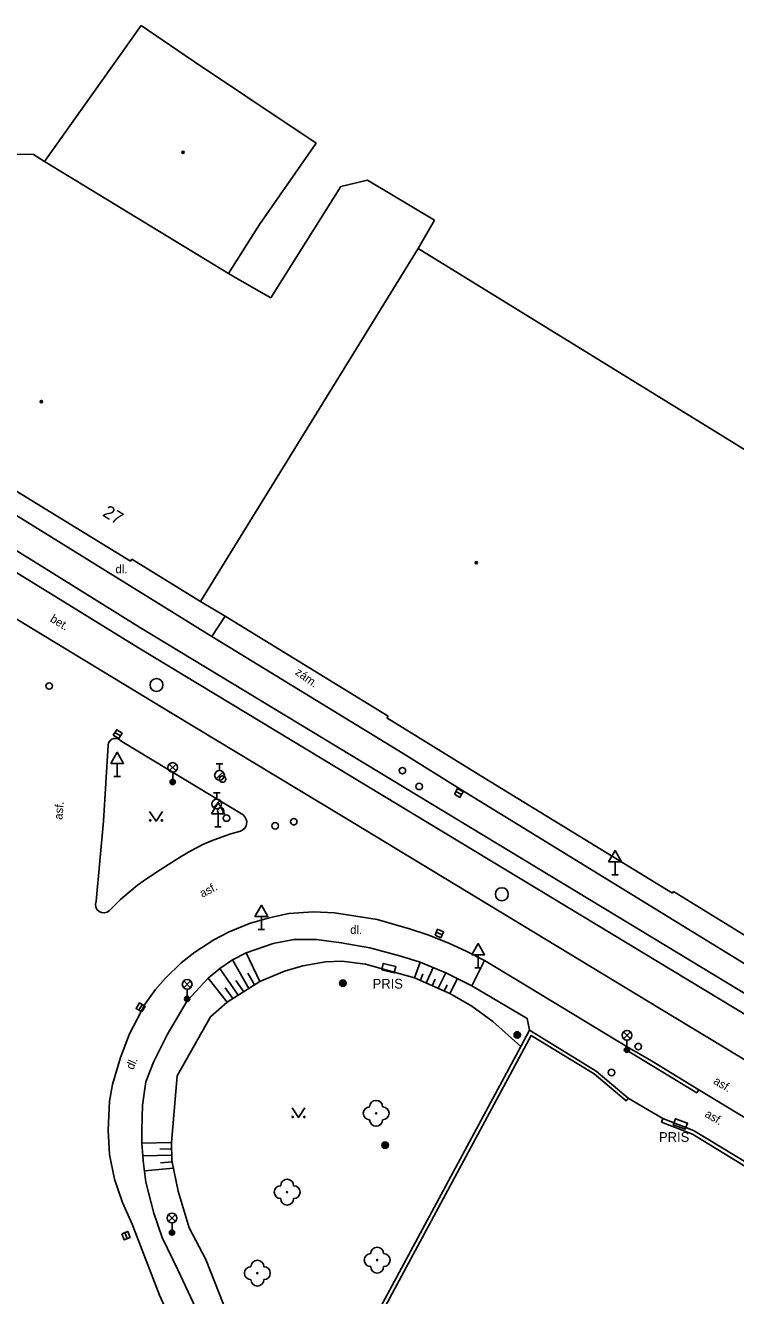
# Model space of a CAD drawing. Extents: x -598341 to -594502, y -1162301 to -1161406.
# Drawn here: x -597632.3 to -597577.4, y -1161626.1 to -1161527.8 of the extents above; entities that cross this region are included whole.
import ezdxf

# ---------------------------------------------------------------- set-up
doc = ezdxf.new("R2010")
doc.units = 0
for name, color, linetype in [('Vrstva 10', 7, 'Continuous'), ('Vrstva 11', 7, 'Continuous'), ('Vrstva 13', 7, 'Continuous'), ('Vrstva 14', 7, 'Continuous'), ('Vrstva 15', 7, 'Continuous'), ('Vrstva 22', 7, 'Continuous'), ('Vrstva 24', 7, 'Continuous'), ('Vrstva 25', 7, 'Continuous'), ('Vrstva 27', 7, 'Continuous'), ('Vrstva 28', 7, 'Continuous'), ('Vrstva 33', 7, 'Continuous'), ('Vrstva 34', 7, 'Continuous'), ('Vrstva 36', 7, 'Continuous'), ('Vrstva 39', 7, 'Continuous'), ('Vrstva 40', 7, 'Continuous'), ('Vrstva 41', 7, 'Continuous'), ('Vrstva 46', 7, 'Continuous'), ('Vrstva 5', 7, 'Continuous'), ('Vrstva 7', 7, 'Continuous'), ('Vrstva 8', 7, 'Continuous')]:
    doc.layers.add(name, color=color, linetype=linetype)

msp = doc.modelspace()

# ---------------------------------------------------------------- linework, layer by layer
at = {"layer": 'Vrstva 10'}
for p, q in [((-597624.88, -1161583.22), (-597615.5, -1161588.89)), ((-597594.17, -1161601.76), (-597596.82, -1161600.16)), ((-597624.07, -1161620.55), (-597621.97, -1161626.04)), ((-597621.97, -1161626.04), (-597612.47, -1161646.5))]:
    msp.add_line(p, q, dxfattribs=at)
for points in [[(-597648.34, -1161556.03), (-597646.18, -1161557.58), (-597617.91, -1161575.1)], [(-597617.91, -1161575.1), (-597603.13, -1161584.15)], [(-597625.93, -1161583.5), (-597625.89, -1161583.33), (-597625.77, -1161583.14), (-597625.64, -1161583.04), (-597625.5, -1161582.99), (-597625.33, -1161582.97), (-597625.16, -1161583.01), (-597624.88, -1161583.22)], [(-597626.86, -1161595.57), (-597626.28, -1161589.39), (-597625.93, -1161583.5)], [(-597603.13, -1161584.15), (-597598.66, -1161586.94), (-597567.48, -1161606.1)], [(-597615.5, -1161588.89), (-597615.35, -1161589.04), (-597615.25, -1161589.24), (-597615.21, -1161589.4), (-597615.23, -1161589.58), (-597615.27, -1161589.75), (-597615.36, -1161589.92), (-597615.51, -1161590.04), (-597615.7, -1161590.16), (-597616.44, -1161590.37), (-597617.17, -1161590.61), (-597617.95, -1161590.91), (-597618.6, -1161591.19), (-597619.53, -1161591.67), (-597620.29, -1161592.11), (-597621.25, -1161592.74), (-597622.28, -1161593.38), (-597623.23, -1161594.02), (-597623.67, -1161594.34), (-597624.3, -1161594.86), (-597624.97, -1161595.43), (-597625.82, -1161596.28), (-597626.01, -1161596.41), (-597626.2, -1161596.46), (-597626.44, -1161596.45), (-597626.63, -1161596.36), (-597626.81, -1161596.2), (-597626.88, -1161596), (-597626.9, -1161595.8), (-597626.86, -1161595.57)], [(-597596.82, -1161600.16), (-597598.2, -1161599.46), (-597599.58, -1161598.83), (-597601.21, -1161598.18), (-597602.63, -1161597.71), (-597605.13, -1161596.99), (-597608.43, -1161596.48), (-597610.06, -1161596.39), (-597611.96, -1161596.53), (-597613.49, -1161596.86), (-597615.01, -1161597.3), (-597616.57, -1161597.93), (-597617.77, -1161598.55), (-597619.23, -1161599.51), (-597620.29, -1161600.34), (-597621.5, -1161601.53), (-597622.27, -1161602.4), (-597623.07, -1161603.51), (-597624.28, -1161605.83), (-597624.98, -1161607.66), (-597625.59, -1161609.75), (-597625.83, -1161611.03), (-597625.94, -1161613.28), (-597625.83, -1161615.16), (-597625.43, -1161617.07), (-597624.82, -1161618.87), (-597624.07, -1161620.55)], [(-597585.79, -1161606.83), (-597594.17, -1161601.76)], [(-597583.92, -1161607.93), (-597585.79, -1161606.83)], [(-597583.92, -1161607.93), (-597580.26, -1161610.16)], [(-597580.26, -1161610.16), (-597573.99, -1161613.95)]]:
    msp.add_lwpolyline(points, dxfattribs=at)
at = {"layer": 'Vrstva 11'}
for p, q in [((-597617.91, -1161575.1), (-597616.89, -1161573.53)), ((-597597.81, -1161602.11), (-597596.82, -1161600.16))]:
    msp.add_line(p, q, dxfattribs=at)
for points in [[(-597631.49, -1161569.4), (-597640.71, -1161563.68), (-597652.22, -1161555.75)], [(-597491.79, -1161654.07), (-597514.39, -1161640.46), (-597547.21, -1161620.56), (-597565.99, -1161609.22), (-597585.64, -1161597.29), (-597623.42, -1161574.41), (-597631.49, -1161569.4)], [(-597597.81, -1161602.11), (-597599.81, -1161601.12), (-597601.81, -1161600.3), (-597603.29, -1161599.83), (-597605.7, -1161599.19), (-597607.91, -1161598.78), (-597609.82, -1161598.54), (-597611.56, -1161598.53), (-597613.18, -1161598.84), (-597615.27, -1161599.56), (-597616.31, -1161600.11), (-597617.29, -1161600.77), (-597618.2, -1161601.53), (-597619.82, -1161603.27), (-597621.35, -1161605.87), (-597622.43, -1161608.03), (-597623.01, -1161609.55), (-597623.27, -1161611.36), (-597623.32, -1161613.28), (-597623.32, -1161614.28), (-597623.26, -1161615.28), (-597623.23, -1161615.65), (-597623.01, -1161617.3), (-597622.4, -1161619.71), (-597621.75, -1161621.59), (-597620.53, -1161624.08)], [(-597593.36, -1161605.56), (-597593.54, -1161604.64), (-597597.81, -1161602.11)], [(-597580.26, -1161610.16), (-597580.42, -1161610.41), (-597585.94, -1161607.04), (-597585.79, -1161606.83)], [(-597620.53, -1161624.08), (-597617.38, -1161630.84), (-597613.49, -1161639.39), (-597612.13, -1161639.96), (-597611.82, -1161639.91)]]:
    msp.add_lwpolyline(points, dxfattribs=at)
at = {"layer": 'Vrstva 13'}
msp.add_line((-597623.58, -1161575.96), (-597524.08, -1161636.17), dxfattribs=at)
for points in [[(-597631.53, -1161571.07), (-597641.52, -1161564.93), (-597646.37, -1161561.72), (-597653.41, -1161556.45)], [(-597654.55, -1161559.44), (-597649.12, -1161563.4), (-597643.66, -1161567.14), (-597639.29, -1161569.92), (-597631.6, -1161574.59)], [(-597623.58, -1161575.96), (-597631.53, -1161571.07)], [(-597631.6, -1161574.59), (-597620.98, -1161581.06)], [(-597525.62, -1161638.79), (-597532.4, -1161634.67), (-597542.09, -1161628.78), (-597553.46, -1161621.89), (-597567.32, -1161613.53), (-597583.27, -1161603.88), (-597607.87, -1161588.96), (-597620.98, -1161581.06)]]:
    msp.add_lwpolyline(points, dxfattribs=at)
at = {"layer": 'Vrstva 14'}
for points in [[(-597618.01, -1161604.51), (-597616.72, -1161603.38), (-597614.19, -1161601.78), (-597612.29, -1161600.99), (-597610.88, -1161600.57), (-597609.12, -1161600.26), (-597607.87, -1161600.22), (-597606.02, -1161600.45), (-597602.24, -1161601.5), (-597599.5, -1161602.72), (-597597.81, -1161603.69), (-597596.19, -1161604.89), (-597594.03, -1161606.81)], [(-597618.37, -1161623.29), (-597619.67, -1161620.83), (-597620.52, -1161618.01), (-597621, -1161615.63), (-597621.04, -1161614.23), (-597620.6, -1161609.08), (-597618.01, -1161604.51)], [(-597618.37, -1161623.29), (-597615.76, -1161629.96), (-597611.15, -1161638.66)]]:
    msp.add_lwpolyline(points, dxfattribs=at)
at = {"layer": 'Vrstva 15'}
for p, q in [((-597614.19, -1161601.78), (-597615.27, -1161599.56)), ((-597615.04, -1161602.32), (-597616.31, -1161600.11)), ((-597602.24, -1161601.5), (-597601.81, -1161600.3)), ((-597616.72, -1161603.38), (-597618.2, -1161601.53)), ((-597615.88, -1161602.85), (-597617.29, -1161600.77)), ((-597614.61, -1161602.05), (-597615.13, -1161601.15)), ((-597601.78, -1161601.71), (-597601.6, -1161601.2)), ((-597601.33, -1161601.91), (-597600.81, -1161600.71)), ((-597600.87, -1161602.11), (-597600.65, -1161601.59)), ((-597600.42, -1161602.31), (-597599.81, -1161601.12)), ((-597599.5, -1161602.72), (-597598.92, -1161601.56)), ((-597616.3, -1161603.11), (-597616.87, -1161602.28)), ((-597615.45, -1161602.58), (-597616.06, -1161601.7)), ((-597599.96, -1161602.52), (-597599.71, -1161602.03)), ((-597621.04, -1161614.23), (-597623.32, -1161614.28)), ((-597621.02, -1161615.23), (-597623.26, -1161615.28)), ((-597621.04, -1161614.73), (-597621.94, -1161614.75)), ((-597620.88, -1161616.22), (-597623.13, -1161616.43)), ((-597620.99, -1161615.73), (-597621.87, -1161615.81))]:
    msp.add_line(p, q, dxfattribs=at)
at = {"layer": 'Vrstva 22'}
for centre in [(-597605.21, -1161611.98), (-597612.09, -1161618.08), (-597605.13, -1161623.34), (-597614.39, -1161624.35)]:
    msp.add_circle(centre, 0.05, dxfattribs=at)
for centre, start, end in [((-597605.71, -1161611.98), 90, 270), ((-597605.21, -1161611.48), 0, 180), ((-597604.71, -1161611.98), 270, 90), ((-597605.21, -1161612.48), 180, 0), ((-597612.09, -1161617.58), 0, 180), ((-597612.59, -1161618.08), 90, 270), ((-597611.59, -1161618.08), 270, 90), ((-597612.09, -1161618.58), 180, 0), ((-597605.63, -1161623.34), 90, 270), ((-597605.13, -1161622.84), 0, 180), ((-597604.63, -1161623.34), 270, 90), ((-597614.89, -1161624.35), 90, 270), ((-597614.39, -1161623.85), 0, 180), ((-597613.89, -1161624.35), 270, 90), ((-597605.13, -1161623.84), 180, 0), ((-597614.39, -1161624.85), 180, 0)]:
    msp.add_arc(centre, 0.5, start, end, dxfattribs=at)
at = {"layer": 'Vrstva 24'}
for points in [[(-597604.776, -1161600.869), (-597603.807, -1161601.116), (-597603.684, -1161600.631), (-597604.653, -1161600.384)], [(-597582.246, -1161612.869), (-597581.31, -1161613.22), (-597581.134, -1161612.752), (-597582.071, -1161612.401)]]:
    msp.add_lwpolyline(points, close=True, dxfattribs=at)
at = {"layer": 'Vrstva 25'}
for centre, radius in [((-597607.78, -1161601.92), 0.25), ((-597607.78, -1161601.92), 0.2), ((-597607.78, -1161601.92), 0.15), ((-597607.78, -1161601.92), 0.1), ((-597607.78, -1161601.92), 0.05), ((-597594.3, -1161605.92), 0.25), ((-597594.3, -1161605.92), 0.2), ((-597594.3, -1161605.92), 0.15), ((-597594.3, -1161605.92), 0.1), ((-597594.3, -1161605.92), 0.05), ((-597604.51, -1161614.45), 0.25), ((-597604.51, -1161614.45), 0.2), ((-597604.51, -1161614.45), 0.15), ((-597604.51, -1161614.45), 0.1), ((-597604.51, -1161614.45), 0.05)]:
    msp.add_circle(centre, radius, dxfattribs=at)
at = {"layer": 'Vrstva 27'}
for p, q in [((-597625.402, -1161582.518), (-597624.978, -1161582.782)), ((-597599.036, -1161587.075), (-597598.604, -1161587.325)), ((-597600.561, -1161597.973), (-597600.099, -1161598.167)), ((-597623.55, -1161604.004), (-597623.29, -1161603.576)), ((-597624.65, -1161621.207), (-597624.47, -1161621.673))]:
    msp.add_line(p, q, dxfattribs=at)
for points in [[(-597625.534, -1161582.73), (-597625.11, -1161582.994), (-597624.846, -1161582.57), (-597625.27, -1161582.306)], [(-597599.162, -1161587.291), (-597598.729, -1161587.542), (-597598.478, -1161587.109), (-597598.911, -1161586.858)], [(-597600.657, -1161598.204), (-597600.196, -1161598.397), (-597600.003, -1161597.936), (-597600.464, -1161597.743)], [(-597623.336, -1161604.134), (-597623.076, -1161603.706), (-597623.504, -1161603.446), (-597623.764, -1161603.874)], [(-597624.883, -1161621.297), (-597624.703, -1161621.763), (-597624.237, -1161621.583), (-597624.417, -1161621.117)]]:
    msp.add_lwpolyline(points, close=True, dxfattribs=at)
for centre in [(-597622.19, -1161578.84), (-597595.49, -1161595.03)]:
    msp.add_circle(centre, 0.5, dxfattribs=at)
at = {"layer": 'Vrstva 28'}
for p, q in [((-597617.578, -1161586.102), (-597617.048, -1161585.572)), ((-597617.57, -1161584.955), (-597617.07, -1161584.955)), ((-597617.32, -1161585.455), (-597617.32, -1161584.955)), ((-597617.788, -1161588.322), (-597617.258, -1161587.792)), ((-597617.78, -1161587.175), (-597617.28, -1161587.175)), ((-597617.53, -1161587.675), (-597617.53, -1161587.175))]:
    msp.add_line(p, q, dxfattribs=at)
for centre, radius in [((-597630.49, -1161578.92), 0.25), ((-597617.32, -1161585.83), 0.375), ((-597617.08, -1161586.12), 0.25), ((-597603.18, -1161585.47), 0.25), ((-597601.88, -1161586.69), 0.25), ((-597617.53, -1161588.05), 0.375), ((-597617.23, -1161588.57), 0.25), ((-597616.78, -1161589.14), 0.25), ((-597613.02, -1161589.74), 0.25), ((-597611.58, -1161589.42), 0.25), ((-597584.94, -1161606.82), 0.25), ((-597587.01, -1161608.82), 0.25)]:
    msp.add_circle(centre, radius, dxfattribs=at)
at = {"layer": 'Vrstva 33'}
for p, q in [((-597621.205, -1161585.49), (-597620.675, -1161584.96)), ((-597621.205, -1161584.96), (-597620.675, -1161585.49)), ((-597620.94, -1161585.6), (-597620.94, -1161586.35)), ((-597620.085, -1161602.27), (-597619.555, -1161601.74)), ((-597620.085, -1161601.74), (-597619.555, -1161602.27)), ((-597619.82, -1161602.38), (-597619.82, -1161603.13)), ((-597586.085, -1161606.21), (-597585.555, -1161605.68)), ((-597586.085, -1161605.68), (-597585.555, -1161606.21)), ((-597585.82, -1161606.32), (-597585.82, -1161607.07)), ((-597621.255, -1161620.35), (-597620.725, -1161619.82)), ((-597621.255, -1161619.82), (-597620.725, -1161620.35)), ((-597620.99, -1161620.46), (-597620.99, -1161621.21))]:
    msp.add_line(p, q, dxfattribs=at)
for centre, radius in [((-597620.94, -1161585.225), 0.375), ((-597620.94, -1161586.35), 0.2), ((-597620.94, -1161586.35), 0.145), ((-597620.94, -1161586.35), 0.0876), ((-597619.82, -1161602.005), 0.375), ((-597619.82, -1161603.13), 0.2), ((-597619.82, -1161603.13), 0.145), ((-597619.82, -1161603.13), 0.0876), ((-597585.82, -1161605.945), 0.375), ((-597585.82, -1161607.07), 0.2), ((-597585.82, -1161607.07), 0.145), ((-597585.82, -1161607.07), 0.0876), ((-597620.99, -1161620.085), 0.375), ((-597620.99, -1161621.21), 0.2), ((-597620.99, -1161621.21), 0.145), ((-597620.99, -1161621.21), 0.0876)]:
    msp.add_circle(centre, radius, dxfattribs=at)
at = {"layer": 'Vrstva 34'}
for p, q in [((-597625.23, -1161584.912), (-597625.23, -1161585.93)), ((-597625.48, -1161585.93), (-597624.98, -1161585.93)), ((-597617.43, -1161588.802), (-597617.43, -1161589.82)), ((-597617.68, -1161589.82), (-597617.18, -1161589.82)), ((-597586.74, -1161592.522), (-597586.74, -1161593.54)), ((-597586.99, -1161593.54), (-597586.49, -1161593.54)), ((-597614.08, -1161596.752), (-597614.08, -1161597.77)), ((-597614.33, -1161597.77), (-597613.83, -1161597.77)), ((-597597.32, -1161599.712), (-597597.32, -1161600.73)), ((-597597.57, -1161600.73), (-597597.07, -1161600.73))]:
    msp.add_line(p, q, dxfattribs=at)
for points in [[(-597625.73, -1161584.912), (-597624.73, -1161584.912), (-597625.23, -1161584.046)], [(-597617.93, -1161588.802), (-597616.93, -1161588.802), (-597617.43, -1161587.936)], [(-597587.24, -1161592.522), (-597586.24, -1161592.522), (-597586.74, -1161591.656)], [(-597614.58, -1161596.752), (-597613.58, -1161596.752), (-597614.08, -1161595.886)], [(-597597.82, -1161599.712), (-597596.82, -1161599.712), (-597597.32, -1161598.846)]]:
    msp.add_lwpolyline(points, close=True, dxfattribs=at)
at = {"layer": 'Vrstva 36'}
for points in [[(-597622.72, -1161588.62), (-597622.22, -1161589.37), (-597621.72, -1161588.62)], [(-597611.71, -1161611.56), (-597611.21, -1161612.31), (-597610.71, -1161611.56)]]:
    msp.add_lwpolyline(points, dxfattribs=at)
for centre in [(-597622.67, -1161589.32), (-597621.771, -1161589.32), (-597611.66, -1161612.259), (-597610.761, -1161612.259)]:
    msp.add_circle(centre, 0.05, dxfattribs=at)
at = {"layer": 'Vrstva 39'}
for centre, radius in [((-597620.14, -1161537.63), 0.09), ((-597620.14, -1161537.63), 0.0398), ((-597631.09, -1161556.92), 0.09), ((-597631.09, -1161556.92), 0.0398), ((-597597.47, -1161569.39), 0.09), ((-597597.47, -1161569.39), 0.0398)]:
    msp.add_circle(centre, radius, dxfattribs=at)
at = {"layer": 'Vrstva 5'}
for p, q in [((-597630.85, -1161538.33), (-597623.38, -1161527.81)), ((-597623.38, -1161527.81), (-597619.97, -1161530.14)), ((-597619.97, -1161530.14), (-597619.25, -1161530.62)), ((-597619.25, -1161530.62), (-597611.24, -1161535.98)), ((-597611.24, -1161535.98), (-597610.03, -1161536.79)), ((-597610.03, -1161536.79), (-597609.84, -1161536.92)), ((-597633.07, -1161537.76), (-597631.71, -1161537.8)), ((-597609.84, -1161536.92), (-597614.22, -1161543.21)), ((-597631.71, -1161537.8), (-597630.85, -1161538.33)), ((-597616.62, -1161547), (-597630.85, -1161538.33)), ((-597613.35, -1161548.9), (-597607.95, -1161540.27)), ((-597607.95, -1161540.27), (-597605.89, -1161539.78)), ((-597605.89, -1161539.78), (-597600.7, -1161542.87)), ((-597614.22, -1161543.21), (-597614.89, -1161544.27)), ((-597600.7, -1161542.87), (-597601.97, -1161545.08)), ((-597614.89, -1161544.27), (-597616.62, -1161547)), ((-597601.97, -1161545.08), (-597618.78, -1161572.38)), ((-597601.97, -1161545.08), (-597571.44, -1161563.88)), ((-597616.62, -1161547), (-597615.76, -1161547.52)), ((-597615.76, -1161547.52), (-597613.35, -1161548.9)), ((-597624.19, -1161569.26), (-597639.14, -1161560.09)), ((-597624.1, -1161569.12), (-597624.19, -1161569.26)), ((-597618.78, -1161572.38), (-597624.1, -1161569.12)), ((-597616.89, -1161573.53), (-597618.78, -1161572.38)), ((-597604.29, -1161581.26), (-597616.89, -1161573.53)), ((-597604.37, -1161581.39), (-597604.29, -1161581.26)), ((-597596.78, -1161586.08), (-597604.37, -1161581.39)), ((-597582.3, -1161594.95), (-597596.78, -1161586.08)), ((-597582.22, -1161594.82), (-597582.3, -1161594.95)), ((-597574.74, -1161599.44), (-597582.22, -1161594.82))]:
    msp.add_line(p, q, dxfattribs=at)
at = {"layer": 'Vrstva 7'}
for p, q in [((-597594.03, -1161606.81), (-597593.36, -1161605.56)), ((-597611.15, -1161638.66), (-597594.03, -1161606.81))]:
    msp.add_line(p, q, dxfattribs=at)
for points in [[(-597593.36, -1161605.56), (-597588.19, -1161608.73), (-597585.73, -1161610.8)], [(-597611.49, -1161639.9), (-597593.22, -1161605.95), (-597588.36, -1161608.93), (-597585.88, -1161611.02), (-597585.73, -1161610.8)], [(-597583.04, -1161612.38), (-597583.14, -1161612.66), (-597580.75, -1161613.59), (-597566.98, -1161622.03)], [(-597583.04, -1161612.38), (-597580.67, -1161613.31), (-597566.79, -1161621.72)]]:
    msp.add_lwpolyline(points, dxfattribs=at)
at = {"layer": 'Vrstva 8'}
msp.add_line((-597583.04, -1161612.38), (-597585.73, -1161610.8), dxfattribs=at)

# ---------------------------------------------------------------- texts
at = {"layer": 'Vrstva 40'}
for p in [(-597625.36, -1161570.2), (-597607.21, -1161598.1)]:
    msp.add_text('dl.', height=0.65, dxfattribs=at).set_placement(p)
for s, height, rotation, p in [('bet.', 0.65, 328.45618, (-597630.47, -1161573.89)), ('zám.', 0.65, 324.44731, (-597611.53, -1161577.98)), ('asf.', 0.6499, 85.38151, (-597629.47, -1161589.28)), ('asf.', 0.65, 27.42006, (-597618.65, -1161595.31)), ('dl.', 0.65, 65.63054, (-597624, -1161608.66)), ('asf.', 0.65, 328.67408, (-597579.19, -1161609.65)), ('asf.', 0.65, 329.03147, (-597579.85, -1161612.2))]:
    msp.add_text(s, height=height, rotation=rotation, dxfattribs=at).set_placement(p)
at = {"layer": 'Vrstva 41'}
for p in [(-597605.48, -1161602.33), (-597583.34, -1161614.19)]:
    msp.add_text('PRIS', height=0.75, dxfattribs=at).set_placement(p)
at = {"layer": 'Vrstva 46'}
msp.add_text('27', height=1, rotation=328.43, dxfattribs=at).set_placement((-597626.43, -1161565.72))

doc.saveas('drawing.dxf')
